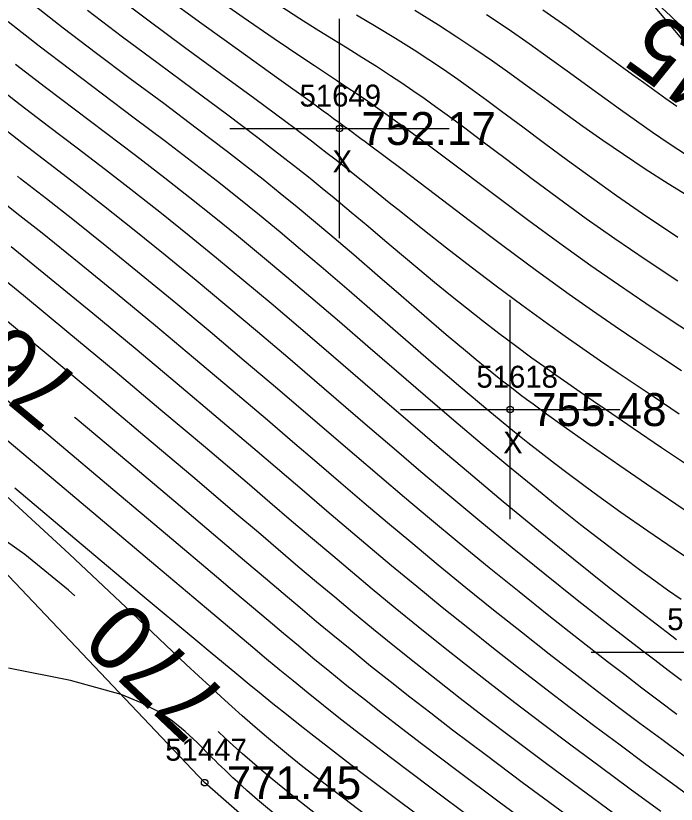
# Model space of a CAD drawing. Extents: x 1378535 to 1380697, y 997729 to 1000024.
# Drawn here: x 1379852.76 to 1379882.87, y 998833.5 to 998869.45 of the extents above; entities that cross this region are included whole.
import ezdxf

# ---------------------------------------------------------------- set-up
doc = ezdxf.new("R2010")
doc.units = 0
for name, color, linetype in [('RD_DTM_BkLn2', 7, 'Continuous'), ('RD_DTM_BkLn_txCode', 7, 'Continuous'), ('RD_DTM_Major1', 7, 'Continuous'), ('RD_DTM_Major1_Lbl', 7, 'Continuous'), ('RD_DTM_Minor1', 7, 'Continuous'), ('RD_EX_H2O', 7, 'Continuous'), ('RD_EX_Misc', 7, 'Continuous'), ('RD_EX_Misc_txCode', 7, 'Continuous'), ('RD_EX_TX_Misc_ELEV', 7, 'Continuous'), ('RD_SMD_Locator', 7, 'Continuous')]:
    doc.layers.add(name, color=color, linetype=linetype)

msp = doc.modelspace()

# ---------------------------------------------------------------- linework, layer by layer
at = {"layer": 'RD_DTM_BkLn2'}
msp.add_lwpolyline([(1380137.104, 998617.435), (1380114.932, 998627.982), (1380110.142, 998637.412), (1380109.582, 998648.354), (1380098.693, 998654.921), (1380088.864, 998651.688), (1380069.259, 998664.275), (1380051.712, 998676.601), (1380045.085, 998683.058), (1380025.38, 998678.361), (1380019.034, 998684.269), (1380023.868, 998692.688), (1380008.939, 998708.879), (1379966.873, 998742.441), (1379939.691, 998764.989), (1379904.79, 998796.424), (1379861.371, 998834.485), (1379829.578, 998867.997), (1379786.438, 998908.428), (1379759.831, 998933.444)], dxfattribs=at)
at = {"layer": 'RD_DTM_Major1'}
for points in [[(1379883.236, 998846.928), (1379881.755, 998847.927), (1379880.295, 998848.928), (1379878.897, 998849.901), (1379877.604, 998850.818), (1379877.275, 998851.054), (1379876.957, 998851.285), (1379876.647, 998851.512), (1379876.344, 998851.735), (1379876.049, 998851.955), (1379875.759, 998852.173), (1379875.353, 998852.483), (1379874.952, 998852.795), (1379874.555, 998853.109), (1379874.157, 998853.428), (1379873.755, 998853.755), (1379873.347, 998854.093), (1379872.381, 998854.907), (1379871.372, 998855.774), (1379870.328, 998856.678), (1379869.258, 998857.607), (1379868.173, 998858.545), (1379867.08, 998859.478), (1379866.333, 998860.106), (1379865.581, 998860.729), (1379864.819, 998861.352), (1379864.041, 998861.977), (1379863.24, 998862.608), (1379862.412, 998863.251), (1379860.991, 998864.33), (1379859.506, 998865.442), (1379857.982, 998866.577), (1379856.445, 998867.728), (1379854.921, 998868.888), (1379853.434, 998870.05)], [(1379882.939, 998857.342), (1379881.494, 998858.301), (1379880.072, 998859.275), (1379878.77, 998860.198), (1379877.507, 998861.118), (1379876.29, 998862.022), (1379875.124, 998862.898), (1379874.014, 998863.734), (1379872.967, 998864.517), (1379872.422, 998864.918), (1379871.893, 998865.303), (1379871.375, 998865.673), (1379870.864, 998866.03), (1379870.356, 998866.378), (1379869.845, 998866.717), (1379869.199, 998867.135), (1379868.54, 998867.551), (1379867.866, 998867.97), (1379867.172, 998868.399), (1379866.456, 998868.844), (1379865.715, 998869.311), (1379864.493, 998870.102)], [(1379882.901, 998837.587), (1379882.096, 998838.195), (1379881.306, 998838.794), (1379880.523, 998839.393), (1379879.739, 998839.998), (1379878.413, 998841.031), (1379877.066, 998842.093), (1379875.706, 998843.179), (1379874.339, 998844.284), (1379872.975, 998845.402), (1379871.621, 998846.527), (1379870.477, 998847.49), (1379869.339, 998848.457), (1379868.199, 998849.431), (1379865.884, 998851.417), (1379864.695, 998852.435), (1379863.178, 998853.724), (1379861.627, 998855.032), (1379860.055, 998856.343), (1379858.478, 998857.644), (1379856.908, 998858.92), (1379855.36, 998860.157), (1379854.163, 998861.098), (1379852.983, 998862.016), (1379852.833, 998862.132)], [(1379882.904, 998829.322), (1379881.114, 998830.625), (1379879.326, 998831.931), (1379877.564, 998833.226), (1379875.851, 998834.493), (1379874.212, 998835.717), (1379872.67, 998836.884), (1379871.676, 998837.645), (1379870.73, 998838.38), (1379869.821, 998839.096), (1379868.939, 998839.801), (1379868.073, 998840.502), (1379867.213, 998841.208), (1379866.476, 998841.821), (1379865.725, 998842.45), (1379864.951, 998843.104), (1379864.142, 998843.789), (1379863.288, 998844.514), (1379862.378, 998845.287), (1379860.251, 998847.089), (1379857.916, 998849.06), (1379855.464, 998851.122), (1379855.437, 998851.145)], [(1379855.453, 998842.998), (1379855.163, 998843.259), (1379853.175, 998844.881), (1379851.122, 998846.324)], [(1379883.354, 998820.678), (1379882.313, 998821.426), (1379881.238, 998822.196), (1379878.602, 998824.082), (1379875.816, 998826.081), (1379872.993, 998828.124), (1379870.246, 998830.143), (1379867.688, 998832.07), (1379865.433, 998833.837), (1379864.929, 998834.246), (1379864.448, 998834.643), (1379863.985, 998835.033), (1379863.537, 998835.417), (1379863.1, 998835.8), (1379862.671, 998836.185), (1379862.309, 998836.516), (1379861.989, 998836.813)]]:
    msp.add_lwpolyline(points, dxfattribs=at)
at = {"layer": 'RD_DTM_Minor1'}
for points in [[(1379883.008, 998851.287), (1379881.864, 998852.055), (1379881.04, 998852.609), (1379880.225, 998853.159), (1379879.416, 998853.709), (1379878.61, 998854.264), (1379877.804, 998854.826), (1379876.994, 998855.401), (1379875.828, 998856.25), (1379874.664, 998857.118), (1379873.516, 998857.992), (1379872.398, 998858.858), (1379871.324, 998859.701), (1379870.309, 998860.508), (1379869.788, 998860.926), (1379869.283, 998861.331), (1379868.788, 998861.729), (1379868.298, 998862.121), (1379867.807, 998862.512), (1379867.309, 998862.904), (1379866.962, 998863.175), (1379866.608, 998863.449), (1379866.244, 998863.729), (1379865.868, 998864.015), (1379865.478, 998864.308), (1379865.074, 998864.612), (1379863.655, 998865.66), (1379862.101, 998866.798), (1379860.459, 998868.003), (1379858.775, 998869.253), (1379857.096, 998870.526)], [(1379883.114, 998853.255), (1379882.119, 998853.913), (1379881.112, 998854.585), (1379880.089, 998855.277), (1379879.049, 998855.994), (1379877.989, 998856.742), (1379876.492, 998857.826), (1379874.968, 998858.958), (1379873.429, 998860.117), (1379871.892, 998861.283), (1379870.371, 998862.436), (1379868.881, 998863.554), (1379868.689, 998863.698), (1379868.496, 998863.84), (1379868.305, 998863.982), (1379868.113, 998864.124), (1379867.922, 998864.265), (1379867.731, 998864.405), (1379867.492, 998864.581), (1379867.252, 998864.756), (1379867.011, 998864.931), (1379866.769, 998865.107), (1379866.526, 998865.284), (1379866.28, 998865.461), (1379864.648, 998866.634), (1379862.958, 998867.846), (1379861.241, 998869.085), (1379859.531, 998870.34)], [(1379883.952, 998854.702), (1379882.727, 998855.501), (1379881.485, 998856.325), (1379880.232, 998857.176), (1379878.973, 998858.053), (1379877.555, 998859.071), (1379876.154, 998860.102), (1379874.79, 998861.123), (1379872.235, 998863.05), (1379871.078, 998863.913), (1379870.676, 998864.209), (1379870.286, 998864.494), (1379869.904, 998864.769), (1379869.529, 998865.036), (1379869.157, 998865.297), (1379868.788, 998865.553), (1379868.324, 998865.869), (1379867.855, 998866.184), (1379867.377, 998866.503), (1379866.886, 998866.829), (1379866.378, 998867.166), (1379865.849, 998867.518), (1379864.539, 998868.402), (1379863.133, 998869.37), (1379861.665, 998870.406)], [(1379883.514, 998848.862), (1379882.195, 998849.753), (1379880.911, 998850.627), (1379879.685, 998851.467), (1379879.081, 998851.882), (1379878.497, 998852.285), (1379877.929, 998852.681), (1379877.374, 998853.07), (1379876.829, 998853.457), (1379876.293, 998853.844), (1379875.534, 998854.402), (1379874.785, 998854.966), (1379874.043, 998855.537), (1379873.308, 998856.115), (1379872.577, 998856.7), (1379871.851, 998857.294), (1379871.096, 998857.92), (1379870.342, 998858.554), (1379869.585, 998859.194), (1379868.823, 998859.839), (1379868.053, 998860.486), (1379867.273, 998861.134), (1379866.732, 998861.577), (1379866.181, 998862.023), (1379865.615, 998862.474), (1379865.031, 998862.933), (1379864.425, 998863.404), (1379863.792, 998863.889), (1379862.366, 998864.961), (1379860.84, 998866.092), (1379859.25, 998867.269), (1379857.633, 998868.475), (1379856.026, 998869.695)], [(1379884.238, 998860.724), (1379882.502, 998861.792), (1379881.46, 998862.462), (1379880.469, 998863.121), (1379879.523, 998863.769), (1379878.614, 998864.408), (1379877.734, 998865.036), (1379876.878, 998865.655), (1379876.076, 998866.237), (1379875.281, 998866.81), (1379874.486, 998867.375), (1379873.684, 998867.931), (1379872.867, 998868.48), (1379872.03, 998869.02), (1379870.946, 998869.684)], [(1379882.898, 998865.314), (1379882.396, 998865.666), (1379881.893, 998866.023), (1379881.386, 998866.388), (1379880.872, 998866.763), (1379879.918, 998867.462), (1379878.921, 998868.191), (1379877.878, 998868.942), (1379876.783, 998869.707)], [(1379883.019, 998869.047), (1379882.626, 998869.425), (1379882.205, 998869.812)], [(1379883.944, 998844.341), (1379882.774, 998845.127), (1379881.569, 998845.953), (1379880.35, 998846.809), (1379879.135, 998847.682), (1379877.946, 998848.562), (1379877.326, 998849.033), (1379876.714, 998849.505), (1379876.107, 998849.982), (1379875.501, 998850.467), (1379874.891, 998850.963), (1379874.274, 998851.472), (1379873.054, 998852.498), (1379871.802, 998853.571), (1379870.529, 998854.673), (1379869.245, 998855.789), (1379867.961, 998856.902), (1379866.688, 998857.996), (1379865.747, 998858.794), (1379864.811, 998859.578), (1379863.873, 998860.351), (1379862.925, 998861.119), (1379861.961, 998861.886), (1379860.972, 998862.658), (1379859.589, 998863.716), (1379858.165, 998864.788), (1379856.719, 998865.873), (1379855.267, 998866.966), (1379853.826, 998868.067), (1379852.414, 998869.172)], [(1379882.937, 998859.34), (1379881.337, 998860.412), (1379880.145, 998861.24), (1379879.005, 998862.054), (1379877.914, 998862.851), (1379876.87, 998863.625), (1379875.869, 998864.373), (1379874.908, 998865.089), (1379874.228, 998865.59), (1379873.563, 998866.075), (1379872.906, 998866.544), (1379872.252, 998867), (1379871.593, 998867.445), (1379870.925, 998867.88), (1379870.071, 998868.415), (1379869.194, 998868.944), (1379868.299, 998869.474)], [(1379883.33, 998863.096), (1379882.545, 998863.618), (1379881.787, 998864.133), (1379881.05, 998864.646), (1379880.328, 998865.158), (1379879.615, 998865.671), (1379878.905, 998866.187), (1379878.006, 998866.843), (1379877.095, 998867.506), (1379876.165, 998868.171), (1379875.211, 998868.835), (1379874.226, 998869.496)], [(1379883.087, 998842.831), (1379882.475, 998843.261), (1379881.844, 998843.713), (1379881.19, 998844.191), (1379880.509, 998844.7), (1379879.535, 998845.443), (1379878.508, 998846.244), (1379877.437, 998847.096), (1379876.327, 998847.995), (1379875.187, 998848.932), (1379874.024, 998849.904), (1379872.734, 998850.996), (1379871.432, 998852.112), (1379870.123, 998853.239), (1379868.814, 998854.37), (1379867.511, 998855.492), (1379866.219, 998856.598), (1379865.111, 998857.537), (1379864.01, 998858.459), (1379862.91, 998859.367), (1379861.805, 998860.265), (1379860.689, 998861.156), (1379859.556, 998862.045), (1379858.216, 998863.075), (1379856.855, 998864.107), (1379855.483, 998865.142), (1379854.11, 998866.183), (1379852.747, 998867.229)], [(1379882.881, 998841), (1379882.67, 998841.159), (1379881.242, 998842.255), (1379879.738, 998843.435), (1379878.179, 998844.681), (1379876.587, 998845.973), (1379874.985, 998847.294), (1379873.395, 998848.624), (1379872.062, 998849.754), (1379870.75, 998850.877), (1379869.456, 998851.99), (1379866.906, 998854.187), (1379865.644, 998855.269), (1379864.4, 998856.325), (1379863.157, 998857.369), (1379861.913, 998858.402), (1379860.664, 998859.422), (1379859.409, 998860.431), (1379858.143, 998861.428), (1379856.855, 998862.425), (1379855.558, 998863.415), (1379854.26, 998864.402), (1379852.964, 998865.392), (1379851.675, 998866.387)], [(1379883.104, 998839.144), (1379882.496, 998839.604), (1379881.892, 998840.064), (1379881.285, 998840.529), (1379879.833, 998841.654), (1379878.36, 998842.812), (1379876.877, 998843.995), (1379875.391, 998845.197), (1379873.912, 998846.41), (1379872.45, 998847.626), (1379871.222, 998848.663), (1379870.006, 998849.699), (1379868.798, 998850.735), (1379866.379, 998852.815), (1379865.156, 998853.862), (1379863.779, 998855.033), (1379862.387, 998856.205), (1379860.984, 998857.373), (1379859.575, 998858.53), (1379858.165, 998859.67), (1379856.758, 998860.787), (1379855.512, 998861.758), (1379854.274, 998862.713), (1379853.042, 998863.658), (1379851.817, 998864.6)], [(1379883.231, 998835.686), (1379882.207, 998836.446), (1379881.214, 998837.187), (1379880.244, 998837.917), (1379879.287, 998838.643), (1379878.335, 998839.373), (1379877.075, 998840.349), (1379875.81, 998841.343), (1379874.543, 998842.352), (1379873.276, 998843.374), (1379872.016, 998844.405), (1379870.763, 998845.443), (1379869.703, 998846.334), (1379868.643, 998847.232), (1379867.575, 998848.144), (1379866.489, 998849.074), (1379865.376, 998850.027), (1379864.229, 998851.008), (1379862.578, 998852.412), (1379860.869, 998853.854), (1379859.127, 998855.311), (1379857.378, 998856.759), (1379855.646, 998858.174), (1379853.958, 998859.532), (1379852.813, 998860.44), (1379851.695, 998861.317)], [(1379883.961, 998833.501), (1379882.703, 998834.424), (1379881.488, 998835.319), (1379880.31, 998836.193), (1379879.16, 998837.052), (1379878.034, 998837.901), (1379876.925, 998838.748), (1379875.727, 998839.673), (1379874.54, 998840.603), (1379873.364, 998841.537), (1379872.197, 998842.476), (1379871.039, 998843.421), (1379869.89, 998844.373), (1379868.913, 998845.191), (1379867.933, 998846.021), (1379866.938, 998846.868), (1379865.918, 998847.739), (1379863.766, 998849.579), (1379861.987, 998851.09), (1379860.12, 998852.667), (1379858.204, 998854.272), (1379856.278, 998855.872), (1379854.381, 998857.43), (1379852.551, 998858.912)], [(1379882.17, 998833.162), (1379880.765, 998834.193), (1379879.396, 998835.203), (1379878.064, 998836.194), (1379876.769, 998837.168), (1379875.509, 998838.125), (1379874.375, 998838.999), (1379873.267, 998839.865), (1379872.18, 998840.725), (1379871.111, 998841.584), (1379870.054, 998842.445), (1379869.005, 998843.311), (1379868.111, 998844.059), (1379867.209, 998844.82), (1379866.288, 998845.602), (1379865.337, 998846.413), (1379864.346, 998847.259), (1379863.304, 998848.147), (1379861.404, 998849.761), (1379859.38, 998851.47), (1379857.287, 998853.227), (1379855.179, 998854.982), (1379853.112, 998856.688), (1379851.139, 998858.296)], [(1379883.257, 998830.717), (1379881.639, 998831.896), (1379880.043, 998833.064), (1379878.48, 998834.214), (1379876.96, 998835.342), (1379875.493, 998836.441), (1379874.09, 998837.505), (1379873.023, 998838.325), (1379871.995, 998839.125), (1379870.998, 998839.913), (1379870.024, 998840.693), (1379869.065, 998841.472), (1379868.112, 998842.257), (1379867.299, 998842.935), (1379866.474, 998843.63), (1379865.626, 998844.347), (1379863.821, 998845.883), (1379862.842, 998846.716), (1379860.825, 998848.427), (1379858.645, 998850.267), (1379856.373, 998852.176), (1379854.081, 998854.09), (1379851.839, 998855.948)], [(1379884.07, 998826.822), (1379882.554, 998827.923), (1379880.597, 998829.346), (1379878.616, 998830.792), (1379876.65, 998832.234), (1379874.74, 998833.644), (1379872.927, 998834.995), (1379871.252, 998836.26), (1379870.338, 998836.959), (1379869.476, 998837.627), (1379868.653, 998838.273), (1379867.858, 998838.905), (1379867.08, 998839.533), (1379866.307, 998840.165), (1379865.643, 998840.715), (1379864.964, 998841.282), (1379864.262, 998841.872), (1379862.745, 998843.154), (1379861.911, 998843.861), (1379859.679, 998845.748), (1379857.193, 998847.846), (1379854.559, 998850.063), (1379851.886, 998852.306)], [(1379883.628, 998825.488), (1379882.209, 998826.519), (1379880.088, 998828.061), (1379877.912, 998829.648), (1379875.74, 998831.239), (1379873.63, 998832.795), (1379871.642, 998834.273), (1379869.836, 998835.634), (1379869.01, 998836.265), (1379868.233, 998836.865), (1379867.495, 998837.442), (1379866.784, 998838.005), (1379866.089, 998838.563), (1379865.399, 998839.125), (1379864.805, 998839.614), (1379864.198, 998840.118), (1379863.569, 998840.644), (1379862.208, 998841.788), (1379861.46, 998842.42), (1379859.141, 998844.377), (1379856.514, 998846.591), (1379853.701, 998848.96), (1379850.82, 998851.38)], [(1379883.908, 998821.953), (1379882.754, 998822.785), (1379881.559, 998823.646), (1379879.119, 998825.402), (1379876.557, 998827.249), (1379873.97, 998829.124), (1379871.452, 998830.966), (1379869.1, 998832.713), (1379867.009, 998834.303), (1379866.374, 998834.797), (1379865.773, 998835.273), (1379865.198, 998835.737), (1379864.641, 998836.195), (1379864.094, 998836.655), (1379863.551, 998837.122), (1379863.084, 998837.532), (1379862.609, 998837.957), (1379862.122, 998838.4), (1379861.616, 998838.865), (1379861.087, 998839.356), (1379860.531, 998839.878), (1379858.049, 998842.23), (1379855.202, 998844.916), (1379852.132, 998847.741)], [(1379883.187, 998824.152), (1379881.876, 998825.105), (1379879.596, 998826.764), (1379877.228, 998828.491), (1379874.849, 998830.233), (1379872.538, 998831.934), (1379870.374, 998833.54), (1379868.435, 998834.998), (1379867.701, 998835.557), (1379867.01, 998836.087), (1379866.354, 998836.597), (1379865.72, 998837.095), (1379865.1, 998837.588), (1379864.483, 998838.084), (1379863.951, 998838.516), (1379863.407, 998838.961), (1379862.843, 998839.425), (1379861.63, 998840.431), (1379860.965, 998840.984), (1379858.529, 998843.018), (1379855.735, 998845.363), (1379852.719, 998847.91)], [(1379865.943, 998831.91), (1379863.776, 998833.703), (1379863.531, 998833.916), (1379863.298, 998834.124), (1379863.074, 998834.325), (1379862.861, 998834.52), (1379862.656, 998834.711), (1379862.46, 998834.896), (1379862.3, 998835.05), (1379862.144, 998835.201), (1379861.994, 998835.349), (1379861.847, 998835.494), (1379861.704, 998835.637), (1379861.025, 998836.313), (1379860.485, 998836.815), (1379859.906, 998837.285), (1379859.25, 998837.723), (1379858.481, 998838.129), (1379857.559, 998838.503), (1379855.262, 998839.148), (1379852.434, 998839.697)]]:
    msp.add_lwpolyline(points, dxfattribs=at)
at = {"layer": 'RD_EX_H2O'}
msp.add_lwpolyline([(1379997.837, 998797.598), (1379973.42, 998798.736), (1379923.913, 998826.394), (1379910.472, 998835.943), (1379903.47, 998840.095), (1379899.036, 998847.157), (1379894.474, 998854.271), (1379896.788, 998858.202), (1379884.516, 998866.738), (1379878.138, 998874.325), (1379875.449, 998884.785), (1379871.598, 998891.084), (1379860.034, 998908.13), (1379856.023, 998913.003), (1379850.337, 998908.19)], dxfattribs=at)
at = {"layer": 'RD_EX_Misc'}
for p, q in [((1379867.515, 998859.31), (1379867.515, 998869.31)), ((1379862.515, 998864.31), (1379872.515, 998864.31)), ((1379875.294, 998846.493), (1379875.294, 998856.493)), ((1379870.294, 998851.493), (1379880.294, 998851.493)), ((1379878.99, 998840.436), (1379888.99, 998840.436))]:
    msp.add_line(p, q, dxfattribs=at)
at = {"layer": 'RD_SMD_Locator'}
for centre in [(1379867.515, 998864.31), (1379875.294, 998851.493), (1379861.371, 998834.485)]:
    msp.add_circle(centre, 0.15, dxfattribs=at)

# ---------------------------------------------------------------- texts
at = {"layer": 'RD_DTM_BkLn_txCode'}
msp.add_text('51447', height=1, dxfattribs=at).set_placement((1379859.576, 998835.485))
at = {"layer": 'RD_DTM_Major1_Lbl'}
for s, rotation, p in [('745', 144.2782, (1379887.507, 998865.819)), ('765', 140.2304, (1379855.922, 998852.705)), ('770', 136.5748, (1379862.613, 998838.348))]:
    msp.add_text(s, height=3, rotation=rotation, dxfattribs=at).set_placement(p)
at = {"layer": 'RD_EX_Misc_txCode'}
for s, p in [('51649', (1379865.696, 998865.31)), ('X', (1379867.2, 998862.31)), ('51618', (1379873.759, 998852.493)), ('X', (1379874.979, 998849.493)), ('51617', (1379882.455, 998841.436))]:
    msp.add_text(s, height=1, dxfattribs=at).set_placement(p)
at = {"layer": 'RD_EX_TX_Misc_ELEV'}
for s, p in [('752.17', (1379868.515, 998863.56)), ('755.48', (1379876.294, 998850.743)), ('771.45', (1379862.371, 998833.735))]:
    msp.add_text(s, height=1.5, dxfattribs=at).set_placement(p)

doc.saveas('drawing.dxf')
